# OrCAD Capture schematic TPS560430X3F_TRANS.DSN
size C; title: TPS560430X3F SIMPLE SWITCHER® 4-V to 36-V, 600-mA; note: Datasheet: SLVSE22B     EVM: SLVUB52; note: Synchronous Step-Down Converter
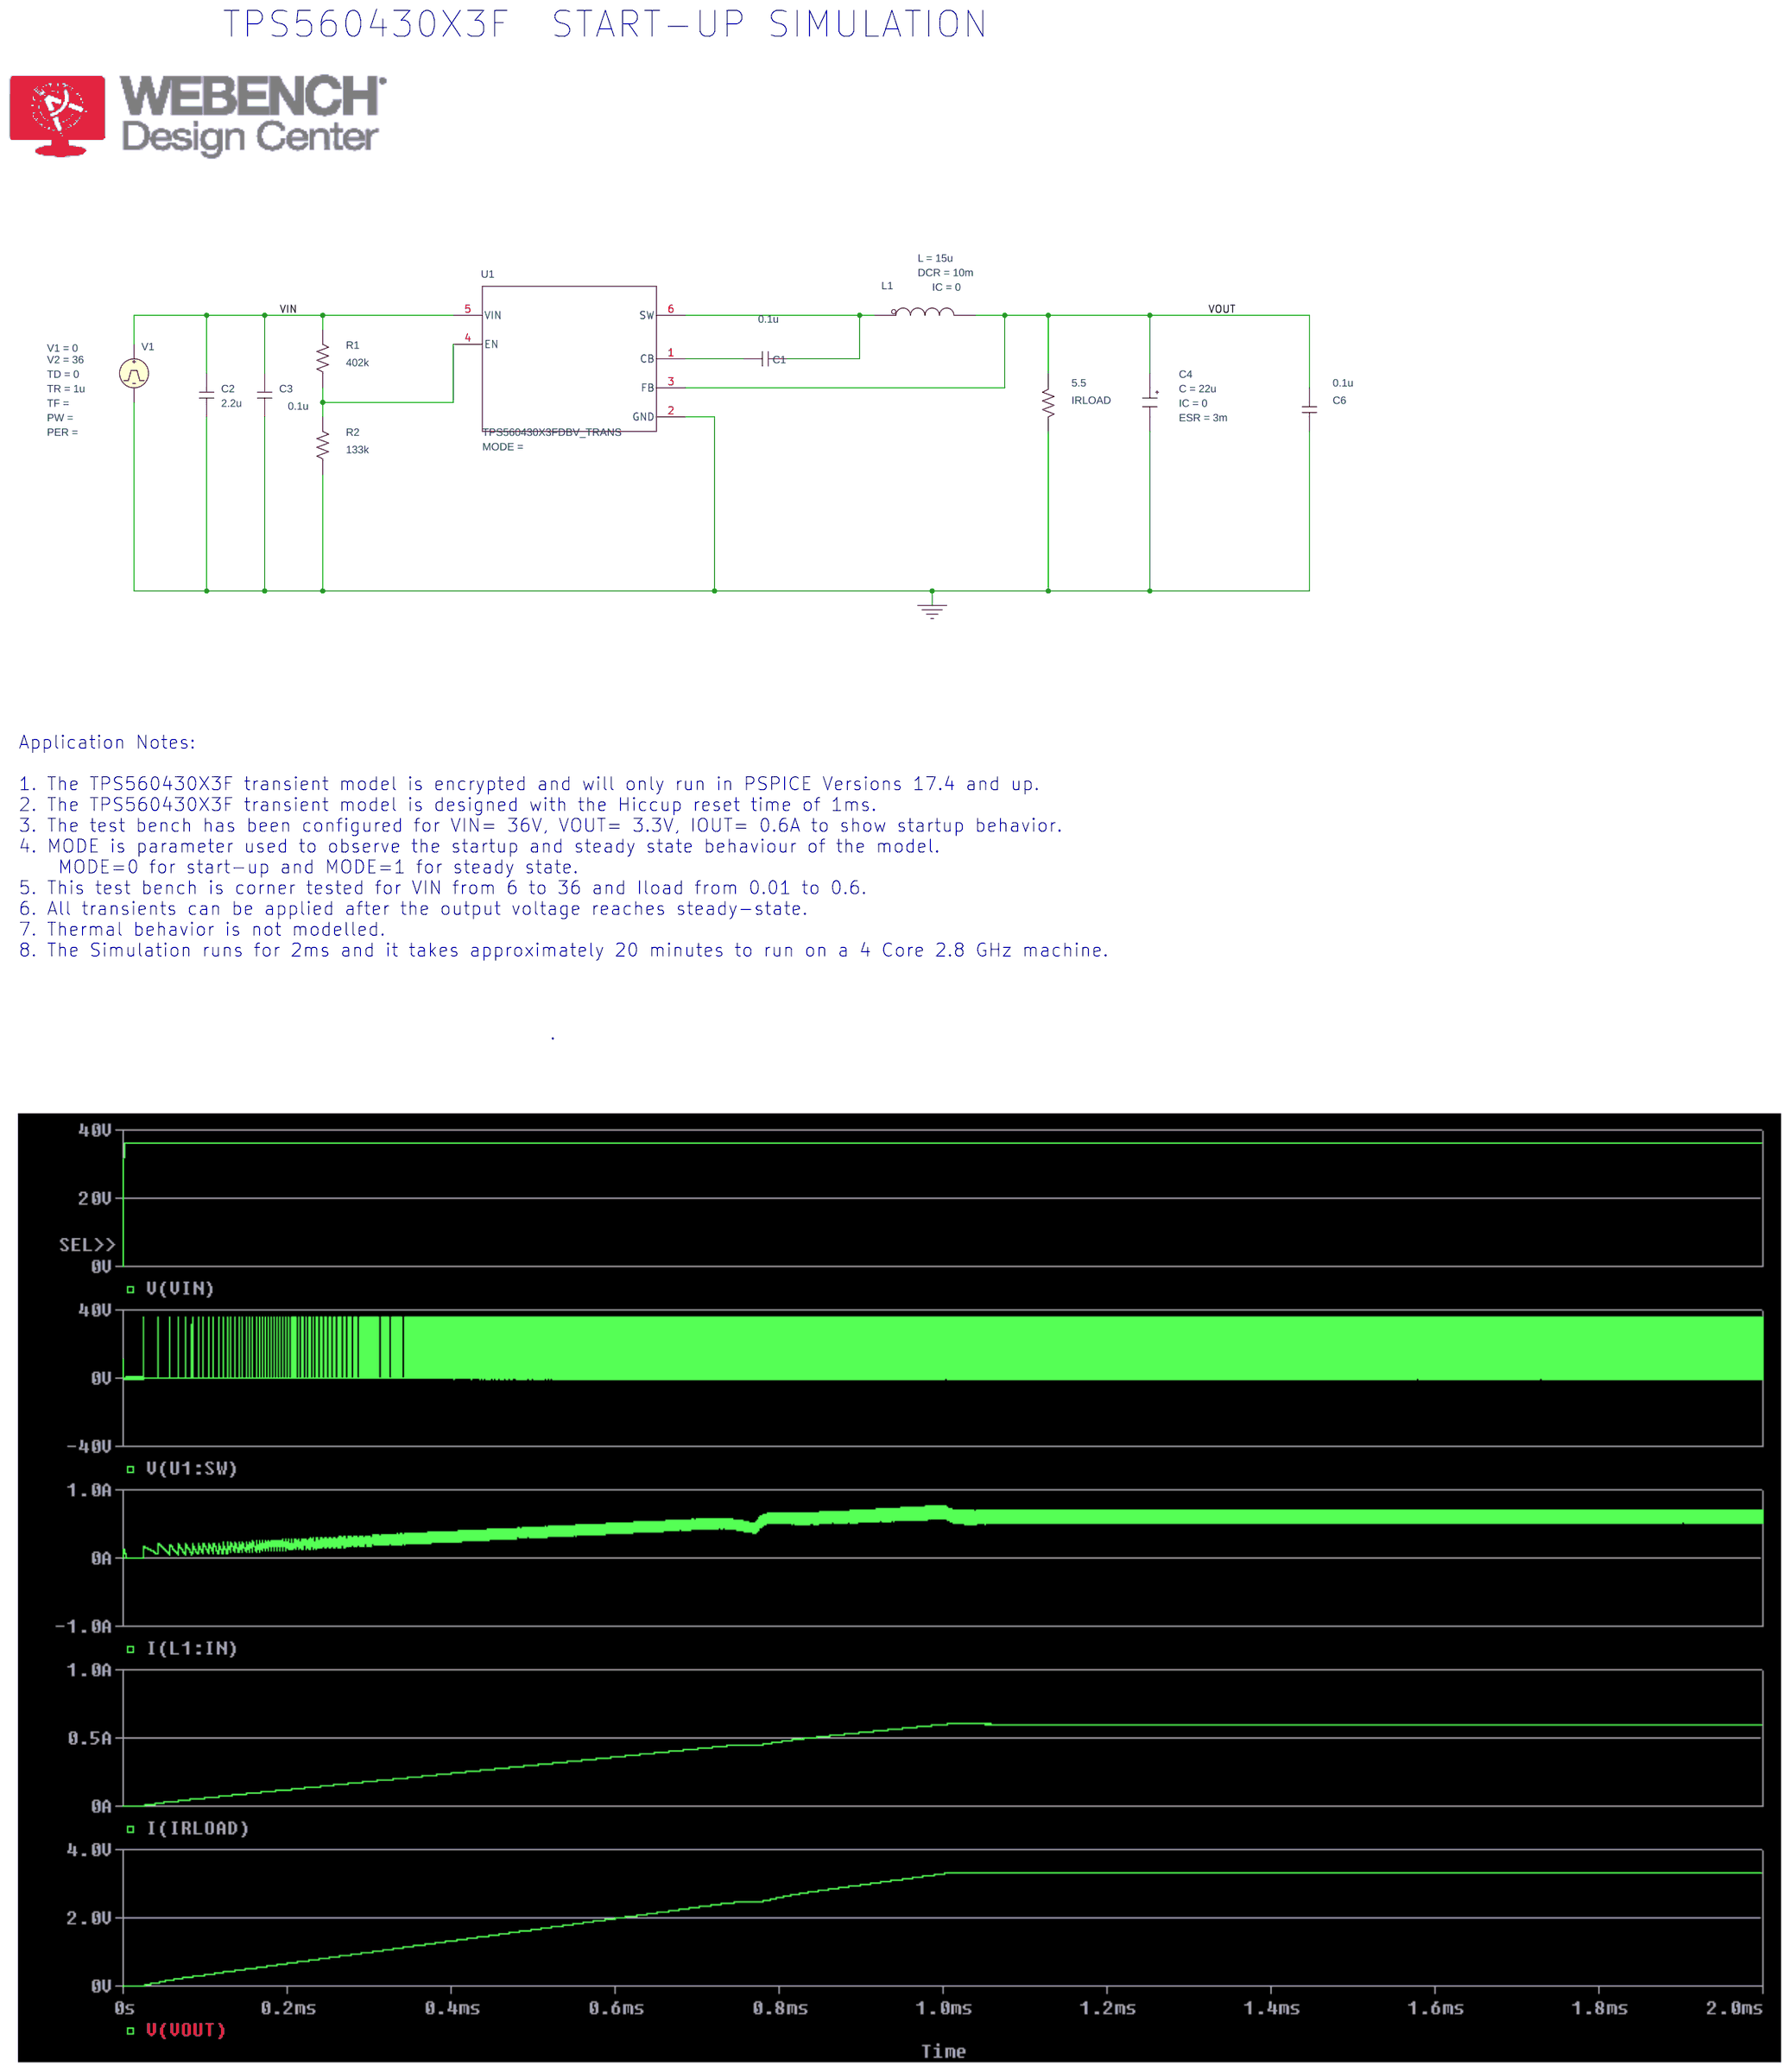
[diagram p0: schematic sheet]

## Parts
C1  0.1u  [RAD/CK05]
C2  2.2u  [RAD/CK05]
C3  0.1u  [RAD/CK05]
C4  CESR
C6  0.1u  [RAD/CK05]
IRLOAD  5.5  [AX/RC05]
L1  LDCR
R1  402k  [AX/RC05]
R2  133k  [AX/RC05]
U1  TPS560430X3FDBV_TRANS  [DBV0006A_N]
V1  VPULSE

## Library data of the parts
C1 = C: IC: -3.3
C2 C3 C6 = C
C4 = CESR_0: C: 22u; ESR: 3m; IC: 0; PSpiceTemplate: X^@REFDES %IN %OUT @MODEL PARAMS:  ?C|C=@C||C=100u|  ?ESR|ESR=@ESR||ESR=0.01| ?X|X=@X||X=2|  ?IC|IC=@IC||IC=2|; X: 1
IRLOAD R1 R2 = R
L1 = LDCR_0: DCR: 10m; IC: 0; L: 15u; PSpiceTemplate: X^@REFDES %IN %OUT @MODEL PARAMS:  ?L|L=@L||L=1u|  ?DCR|DCR=@DCR||DCR=0.01| ?IC|IC=@IC||IC=0|
U1 = TPS560430X3FDBV_TRANS
V1 = VPULSE: TD: 0; TR: 1u; V1: 0; V2: 36

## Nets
VIN: C2.2 C3.2 R1.2 U1.5(VIN) V1.1(+)
0: C2.1 C3.1 C4.3(OUT) C6.2 IRLOAD.2 R2.1 U1.2(GND) V1.2(-)
VOUT: C4.1(IN) C6.1 IRLOAD.1 L1.3(OUT) U1.3(FB)
N16768953: R1.1 R2.2 U1.4(EN)
N16769065: C1.2 L1.1(IN) U1.6(SW)
N16773192: C1.1 U1.1(CB)

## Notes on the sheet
- TPS560430X3F  START-UP SIMULATION
- Application Notes:
  1. The TPS560430X3F transient model is encrypted and will only run in PSPICE Versions 17.4 and up.
  2. The TPS560430X3F transient model is designed with the Hiccup reset time of 1ms.
  3. The test bench has been configured for VIN= 36V, VOUT= 3.3V, IOUT= 0.6A to show startup behavior.
  4. MODE is parameter used to observe the startup and steady state behaviour of the model.
      MODE=0 for start-up and MODE=1 for steady state.
  5. This test bench is corner tested for VIN from 6 to 36 and Iload from 0.01 to 0.6.
  6. All transients can be applied after the output voltage reaches steady-state.
  7. Thermal behavior is not modelled.
  8. The Simulation runs for 2ms and it takes approximately 20 minutes to run on a 4 Core 2.8 GHz machine.
                                                        .
